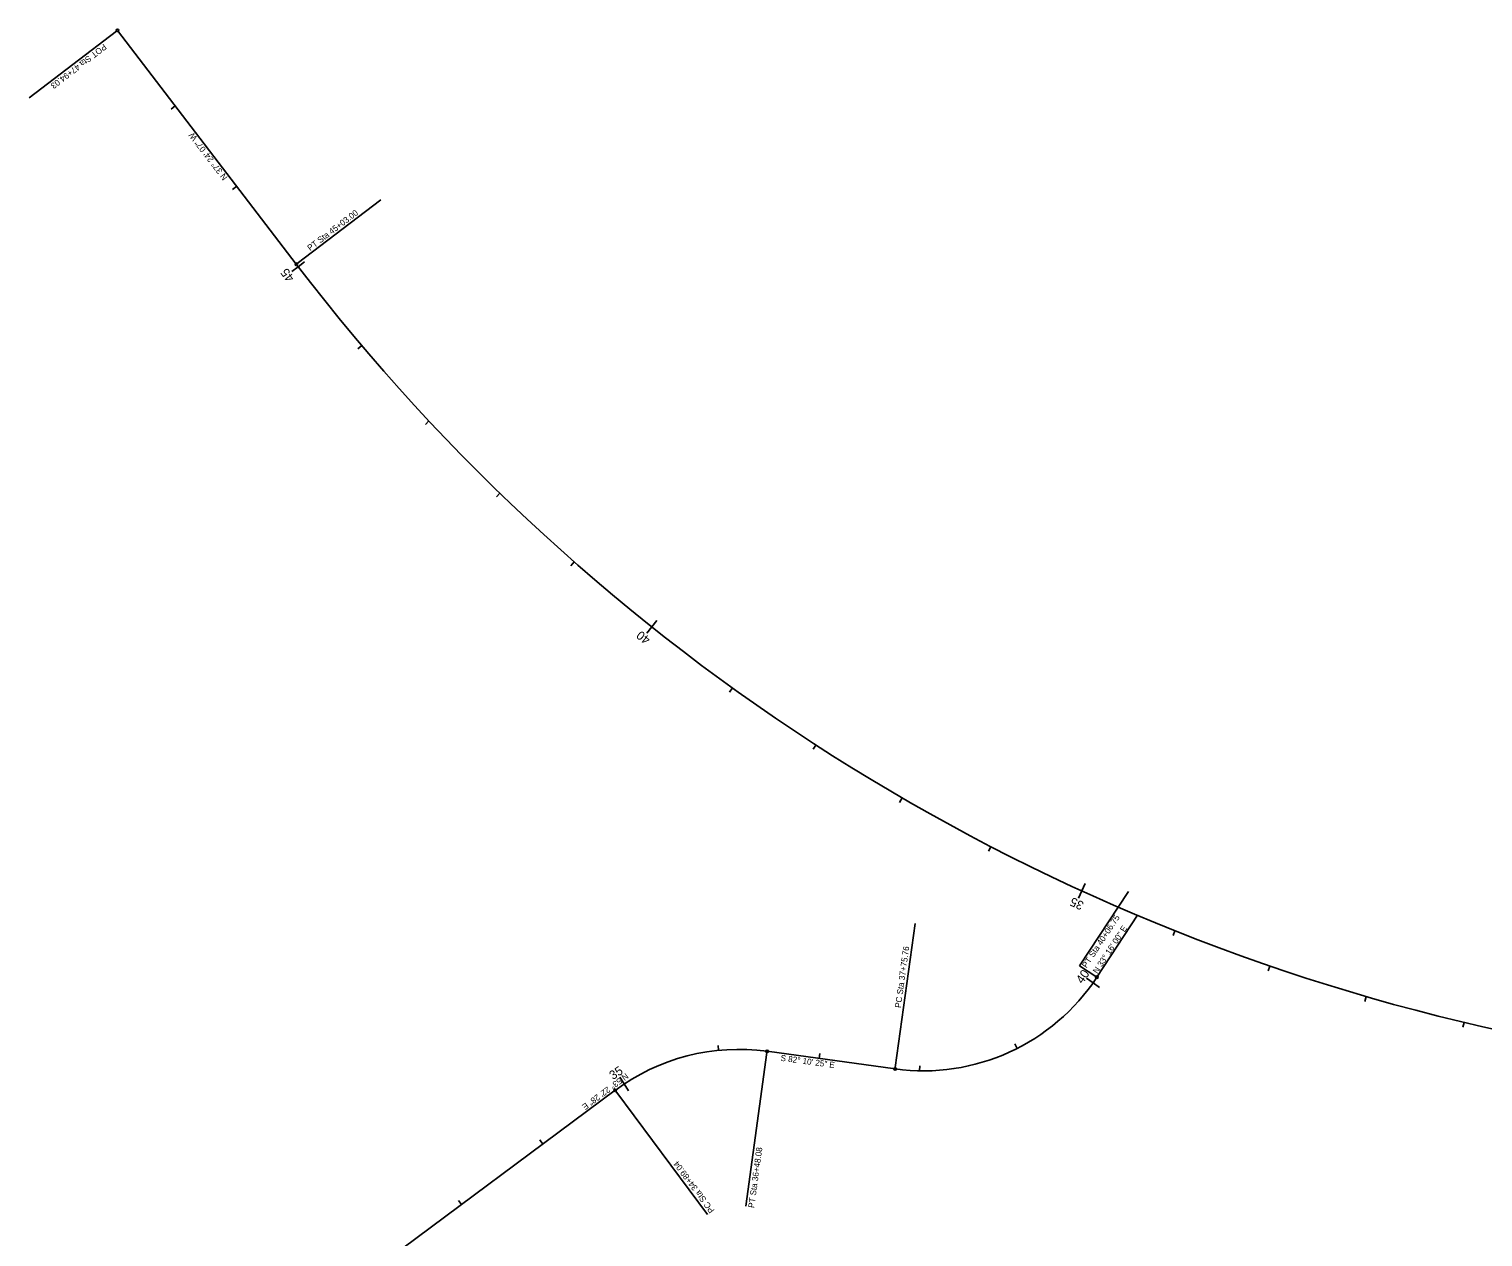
# Model space of a CAD drawing. Extents: x 1612377 to 1619444, y 1093143 to 1096386.
# Drawn here: x 1612436 to 1613872, y 1095192 to 1096386 of the extents above; entities that cross this region are included whole.
import ezdxf

# ---------------------------------------------------------------- set-up
doc = ezdxf.new("R2010")
doc.units = 0
for name, color, linetype in [('RD_GPK_Profile_Cell', 7, 'Continuous'), ('RD_HC_TX_Sta50', 7, 'Continuous'), ('RD_HY_Area_SS', 7, 'Continuous'), ('RD_PD_DR_Ditch', 7, 'Continuous'), ('RD_TX_Drainage', 7, 'Continuous')]:
    doc.layers.add(name, color=color, linetype=linetype)

msp = doc.modelspace()

# ---------------------------------------------------------------- linework, layer by layer
at = {"layer": 'RD_HC_TX_Sta50'}
for p, q in [((1612699.6, 1096153.3), (1612522.9, 1096384.4)), ((1613490.7, 1095448.8), (1613530.7, 1095509.9)), ((1613164.9, 1095375.5), (1613291.4, 1095358.1)), ((1612464.4, 1094928), (1613014.6, 1095337))]:
    msp.add_line(p, q, dxfattribs=at)
for centre, radius, start, end in [((1614328.1, 1097398.4), 2050, 217.402, 257.7882), ((1613319.3, 1095561.2), 205, 262.1737, 326.7332), ((1613136.9, 1095172.4), 205, 82.1737, 126.6256)]:
    msp.add_arc(centre, radius, start, end, dxfattribs=at)
at = {"layer": 'RD_HY_Area_SS'}
for p, q in [((1612521.9, 1096383.7), (1612435.5, 1096317.7)), ((1612700.6, 1096154), (1612783, 1096217)), ((1613521.8, 1095533.3), (1613473.6, 1095460)), ((1613291.5, 1095359.4), (1613311.1, 1095501.7)), ((1613489.6, 1095449.5), (1613473.6, 1095460)), ((1613164.7, 1095374.3), (1613143.8, 1095222.5)), ((1613015.4, 1095336), (1613106, 1095214.1))]:
    msp.add_line(p, q, dxfattribs=at)
for centre in [(1612522.9, 1096384.4), (1612699.6, 1096153.3), (1613490.7, 1095448.8), (1613164.9, 1095375.5), (1613291.4, 1095358.1), (1613014.6, 1095337)]:
    msp.add_circle(centre, 1.25, dxfattribs=at)
at = {"layer": 'RD_TX_Drainage'}
for p, q in [((1612580, 1096309.7), (1612576, 1096306.7)), ((1612640.7, 1096230.3), (1612636.7, 1096227.3)), ((1612701.5, 1096150.9), (1612707.8, 1096155.7)), ((1612701.5, 1096150.9), (1612695.1, 1096146)), ((1612764.2, 1096073), (1612760.4, 1096069.8)), ((1612830.7, 1095998.4), (1612827.1, 1095994.9)), ((1612900.8, 1095927), (1612897.3, 1095923.4)), ((1612974.2, 1095859.2), (1612970.9, 1095855.4)), ((1613050.9, 1095795), (1613055.9, 1095801.2)), ((1613050.9, 1095795), (1613045.9, 1095788.7)), ((1613130.6, 1095734.6), (1613127.7, 1095730.5)), ((1613213.1, 1095678.2), (1613210.4, 1095674)), ((1613298.3, 1095625.9), (1613295.8, 1095621.5)), ((1613386, 1095577.7), (1613383.7, 1095573.3)), ((1613475.9, 1095534), (1613479.2, 1095541.2)), ((1613475.9, 1095534), (1613472.6, 1095526.7)), ((1613567.8, 1095494.6), (1613566, 1095490)), ((1613661.6, 1095459.8), (1613659.9, 1095455.1)), ((1613486.9, 1095443.2), (1613480.3, 1095447.8)), ((1613486.9, 1095443.2), (1613493.4, 1095438.6)), ((1613756.9, 1095429.6), (1613755.5, 1095424.8)), ((1613853.6, 1095404.1), (1613852.4, 1095399.3)), ((1613116.9, 1095376.5), (1613116.4, 1095381.4)), ((1613412, 1095378.4), (1613409.7, 1095382.9)), ((1613216.3, 1095368.5), (1613217, 1095373.4)), ((1613315.5, 1095356.3), (1613315.6, 1095361.3)), ((1613023.6, 1095343.3), (1613019.2, 1095349.9)), ((1613023.6, 1095343.3), (1613028, 1095336.6)), ((1612943.2, 1095283.8), (1612940.2, 1095287.9)), ((1612862.9, 1095224.2), (1612860, 1095228.2))]:
    msp.add_line(p, q, dxfattribs=at)

# ---------------------------------------------------------------- texts
at = {"layer": 'RD_GPK_Profile_Cell'}
for s, rotation, p in [('N 37%%d 24\' 07" W', 127.402, (1612632, 1096239.1)), ('N 33%%d 16\' 00" E', 56.7332, (1613491.2, 1095451.7)), ('S 82%%d 10\' 25" E', 352.1737, (1613177.8, 1095366.2)), ('N 53%%d 22\' 28" E', 216.6256, (1613025, 1095354.4))]:
    msp.add_text(s, height=6, rotation=rotation, dxfattribs=at).set_placement(p)
at = {"layer": 'RD_HY_Area_SS'}
for s, rotation, p in [('POT Sta 47+94.03', 217.402, (1612509.2, 1096371.5)), ('PT Sta 45+03.00', 37.402, (1612713.3, 1096166.2)), ('PT Sta 40+06.75', 56.7332, (1613480.5, 1095457.3)), ('PC Sta 37+75.76', 82.1737, (1613297, 1095418.1)), ('PT Sta 36+48.08', 82.1737, (1613152, 1095220.4)), ('PC Sta 34+89.04', 126.6256, (1613113.2, 1095218.4))]:
    msp.add_text(s, height=6, rotation=rotation, dxfattribs=at).set_placement(p)
at = {"layer": 'RD_PD_DR_Ditch'}
for s, rotation, p in [('45', 127.4859, (1612698.2, 1096139.9)), ('40', 141.4605, (1613050.3, 1095783.6)), ('35', 155.4351, (1613478.6, 1095522.6)), ('40', 54.8468, (1613476.4, 1095441.6)), ('35', 33.561, (1613012.5, 1095347))]:
    msp.add_text(s, height=8.75, rotation=rotation, dxfattribs=at).set_placement(p)

doc.saveas('drawing.dxf')
